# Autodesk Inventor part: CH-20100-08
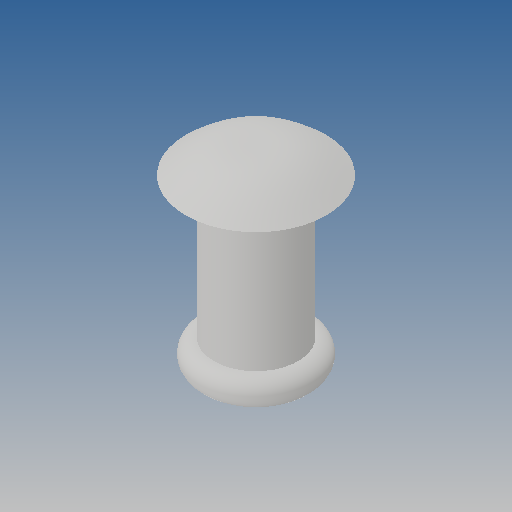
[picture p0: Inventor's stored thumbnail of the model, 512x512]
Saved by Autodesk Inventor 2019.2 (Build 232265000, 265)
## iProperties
Created: 2012-09
Part Number: CH-20100-08
Material: Ogólny
Document SubType Name: Modeling
Designer: CADENGINEERING4
Density: 1 g/cm^3
Appearance: Domyślna
Author: CADENGINEERING4
Revision Number: ÈÎºÎ
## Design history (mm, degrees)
feature "Ô²½Ç2"
node "Bryła1"
